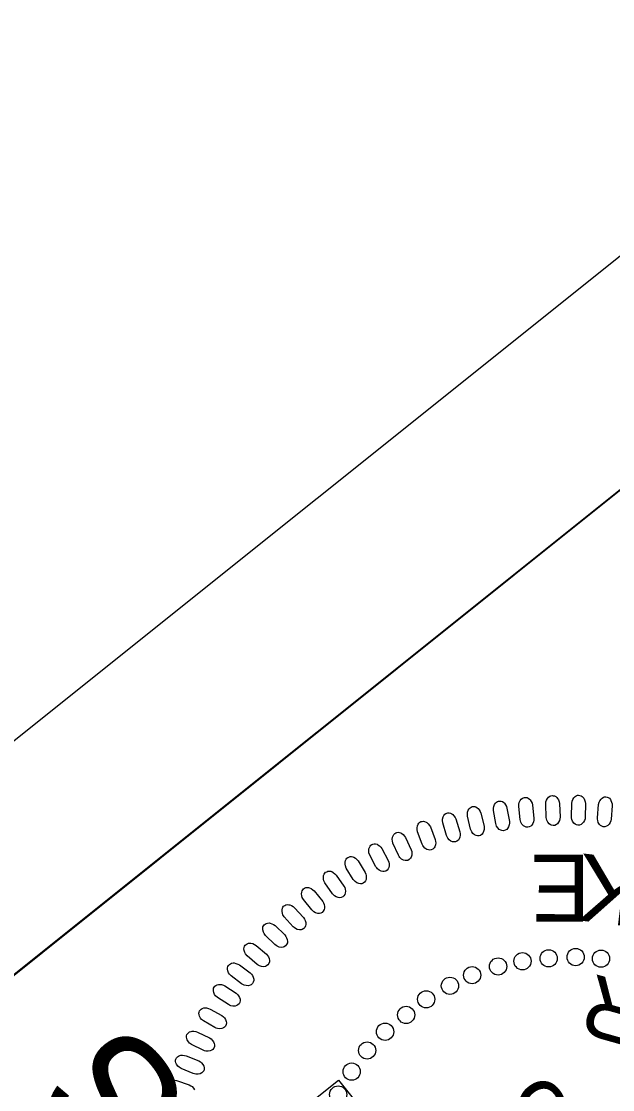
# Model space of a CAD drawing. Extents: x 473437 to 475344, y 504319 to 506318.
# Drawn here: x 473525.9 to 473580.9, y 505671.2 to 505770.6 of the extents above; entities that cross this region are included whole.
import ezdxf

# ---------------------------------------------------------------- set-up
doc = ezdxf.new("R2010")
doc.units = 0
for name, color, linetype in [('Sheet PE Seal Cell', 7, 'Continuous'), ('Sheet Plan CELL', 7, 'Continuous'), ('Sheet Plot Border Outside CELL', 7, 'Continuous'), ('Sheet Sticker Incomplete CELL', 7, 'Continuous')]:
    doc.layers.add(name, color=color, linetype=linetype)

msp = doc.modelspace()

# ---------------------------------------------------------------- linework, layer by layer
at = {"layer": 'Sheet PE Seal Cell'}
for points in [[(473572.264, 505696.325), (473572.13, 505697.544), (473572.143, 505697.766), (473572.179, 505697.911), (473572.273, 505698.092), (473572.357, 505698.211), (473572.461, 505698.303), (473572.56, 505698.353), (473572.67, 505698.385), (473572.783, 505698.378), (473572.905, 505698.361), (473573.016, 505698.313), (473573.13, 505698.225), (473573.199, 505698.153), (473573.282, 505698.011), (473573.361, 505697.839), (473573.401, 505697.683), (473573.545, 505696.434), (473573.541, 505696.264), (473573.511, 505696.12), (473573.44, 505695.952), (473573.344, 505695.801), (473573.256, 505695.711), (473573.106, 505695.634), (473572.959, 505695.598), (473572.807, 505695.622), (473572.697, 505695.66), (473572.56, 505695.745), (473572.423, 505695.9), (473572.336, 505696.072), (473572.292, 505696.197)], [(473574.687, 505696.522), (473574.631, 505697.747), (473574.658, 505697.968), (473574.703, 505698.11), (473574.808, 505698.284), (473574.9, 505698.398), (473575.009, 505698.484), (473575.11, 505698.528), (473575.222, 505698.553), (473575.335, 505698.538), (473575.456, 505698.514), (473575.563, 505698.46), (473575.671, 505698.364), (473575.736, 505698.287), (473575.81, 505698.141), (473575.878, 505697.964), (473575.908, 505697.806), (473575.973, 505696.552), (473575.959, 505696.381), (473575.92, 505696.24), (473575.838, 505696.076), (473575.733, 505695.931), (473575.639, 505695.847), (473575.485, 505695.78), (473575.337, 505695.754), (473575.186, 505695.786), (473575.079, 505695.831), (473574.947, 505695.925), (473574.82, 505696.088), (473574.744, 505696.265), (473574.709, 505696.393)], [(473577.034, 505696.6), (473577.054, 505697.826), (473577.095, 505698.045), (473577.149, 505698.184), (473577.264, 505698.352), (473577.363, 505698.46), (473577.477, 505698.538), (473577.582, 505698.576), (473577.695, 505698.593), (473577.806, 505698.571), (473577.925, 505698.54), (473578.028, 505698.479), (473578.132, 505698.377), (473578.19, 505698.296), (473578.255, 505698.145), (473578.312, 505697.965), (473578.332, 505697.805), (473578.319, 505696.548), (473578.293, 505696.379), (473578.246, 505696.241), (473578.154, 505696.083), (473578.04, 505695.945), (473577.94, 505695.867), (473577.783, 505695.809), (473577.633, 505695.793), (473577.484, 505695.835), (473577.38, 505695.886), (473577.255, 505695.988), (473577.138, 505696.159), (473577.074, 505696.34), (473577.046, 505696.47)], [(473579.444, 505696.487), (473579.541, 505697.71), (473579.595, 505697.926), (473579.659, 505698.061), (473579.784, 505698.221), (473579.89, 505698.322), (473580.008, 505698.393), (473580.115, 505698.424), (473580.229, 505698.435), (473580.339, 505698.407), (473580.456, 505698.367), (473580.555, 505698.3), (473580.651, 505698.191), (473580.705, 505698.107), (473580.76, 505697.953), (473580.806, 505697.769), (473580.815, 505697.608), (473580.723, 505696.355), (473580.687, 505696.188), (473580.631, 505696.052), (473580.529, 505695.9), (473580.407, 505695.77), (473580.303, 505695.698), (473580.142, 505695.65), (473579.991, 505695.643), (473579.846, 505695.695), (473579.745, 505695.753), (473579.626, 505695.862), (473579.521, 505696.04), (473579.468, 505696.225), (473579.448, 505696.356)], [(473567.65, 505695.432), (473567.365, 505696.625), (473567.351, 505696.847), (473567.368, 505696.995), (473567.438, 505697.186), (473567.507, 505697.315), (473567.598, 505697.419), (473567.69, 505697.482), (473567.795, 505697.527), (473567.908, 505697.534), (473568.032, 505697.532), (473568.147, 505697.499), (473568.272, 505697.426), (473568.349, 505697.363), (473568.449, 505697.233), (473568.549, 505697.072), (473568.608, 505696.922), (473568.908, 505695.702), (473568.926, 505695.532), (473568.914, 505695.385), (473568.864, 505695.21), (473568.787, 505695.048), (473568.712, 505694.948), (473568.573, 505694.853), (473568.432, 505694.798), (473568.278, 505694.802), (473568.164, 505694.827), (473568.017, 505694.894), (473567.861, 505695.031), (473567.754, 505695.19), (473567.695, 505695.309)], [(473569.982, 505695.955), (473569.773, 505697.164), (473569.772, 505697.386), (473569.799, 505697.533), (473569.881, 505697.719), (473569.958, 505697.844), (473570.055, 505697.942), (473570.151, 505697.999), (473570.258, 505698.038), (473570.372, 505698.037), (473570.495, 505698.028), (473570.607, 505697.987), (473570.728, 505697.907), (473570.801, 505697.839), (473570.893, 505697.702), (473570.982, 505697.535), (473571.032, 505697.383), (473571.255, 505696.145), (473571.262, 505695.975), (473571.241, 505695.829), (473571.18, 505695.657), (473571.093, 505695.5), (473571.011, 505695.405), (473570.867, 505695.319), (473570.723, 505695.274), (473570.569, 505695.288), (473570.457, 505695.32), (473570.315, 505695.396), (473570.168, 505695.542), (473570.071, 505695.708), (473570.019, 505695.83)], [(473565.421, 505694.829), (473565.061, 505696.001), (473565.033, 505696.222), (473565.041, 505696.371), (473565.099, 505696.566), (473565.16, 505696.699), (473565.244, 505696.808), (473565.332, 505696.877), (473565.433, 505696.929), (473565.546, 505696.943), (473565.669, 505696.949), (473565.787, 505696.923), (473565.916, 505696.858), (473565.997, 505696.799), (473566.105, 505696.676), (473566.215, 505696.522), (473566.283, 505696.376), (473566.659, 505695.177), (473566.687, 505695.008), (473566.685, 505694.862), (473566.646, 505694.683), (473566.58, 505694.517), (473566.511, 505694.411), (473566.378, 505694.308), (473566.241, 505694.246), (473566.086, 505694.24), (473565.971, 505694.257), (473565.821, 505694.315), (473565.657, 505694.442), (473565.539, 505694.594), (473565.473, 505694.709)], [(473563.142, 505694.03), (473562.709, 505695.179), (473562.667, 505695.397), (473562.666, 505695.546), (473562.711, 505695.745), (473562.763, 505695.881), (473562.841, 505695.996), (473562.924, 505696.07), (473563.022, 505696.128), (473563.134, 505696.149), (473563.257, 505696.163), (473563.375, 505696.144), (473563.509, 505696.087), (473563.593, 505696.034), (473563.708, 505695.917), (473563.828, 505695.771), (473563.905, 505695.629), (473564.355, 505694.456), (473564.394, 505694.29), (473564.401, 505694.143), (473564.374, 505693.962), (473564.318, 505693.792), (473564.255, 505693.683), (473564.129, 505693.572), (473563.996, 505693.5), (473563.843, 505693.485), (473563.727, 505693.495), (473563.573, 505693.543), (473563.401, 505693.66), (473563.275, 505693.804), (473563.202, 505693.915)], [(473560.936, 505692.999), (473560.432, 505694.118), (473560.377, 505694.333), (473560.366, 505694.481), (473560.399, 505694.682), (473560.443, 505694.822), (473560.513, 505694.941), (473560.591, 505695.02), (473560.685, 505695.084), (473560.795, 505695.112), (473560.917, 505695.134), (473561.037, 505695.123), (473561.173, 505695.075), (473561.261, 505695.027), (473561.384, 505694.917), (473561.512, 505694.779), (473561.598, 505694.643), (473562.121, 505693.5), (473562.17, 505693.336), (473562.186, 505693.19), (473562.17, 505693.008), (473562.125, 505692.835), (473562.07, 505692.722), (473561.951, 505692.603), (473561.823, 505692.523), (473561.67, 505692.498), (473561.554, 505692.501), (473561.397, 505692.539), (473561.219, 505692.645), (473561.083, 505692.781), (473561.004, 505692.887)], [(473558.84, 505691.938), (473558.268, 505693.022), (473558.198, 505693.234), (473558.178, 505693.381), (473558.199, 505693.584), (473558.234, 505693.727), (473558.295, 505693.85), (473558.369, 505693.934), (473558.459, 505694.004), (473558.567, 505694.038), (473558.687, 505694.068), (473558.808, 505694.064), (473558.947, 505694.024), (473559.037, 505693.982), (473559.166, 505693.881), (473559.303, 505693.75), (473559.397, 505693.62), (473559.991, 505692.512), (473560.051, 505692.352), (473560.076, 505692.207), (473560.071, 505692.024), (473560.037, 505691.849), (473559.989, 505691.733), (473559.878, 505691.606), (473559.755, 505691.519), (473559.604, 505691.484), (473559.488, 505691.479), (473559.33, 505691.508), (473559.145, 505691.602), (473559.001, 505691.73), (473558.915, 505691.831)], [(473556.729, 505690.756), (473556.089, 505691.803), (473556.006, 505692.009), (473555.978, 505692.156), (473555.984, 505692.359), (473556.01, 505692.504), (473556.065, 505692.63), (473556.133, 505692.718), (473556.219, 505692.794), (473556.324, 505692.835), (473556.442, 505692.872), (473556.562, 505692.876), (473556.704, 505692.845), (473556.796, 505692.809), (473556.932, 505692.716), (473557.076, 505692.594), (473557.179, 505692.47), (473557.841, 505691.401), (473557.911, 505691.245), (473557.945, 505691.102), (473557.951, 505690.92), (473557.929, 505690.742), (473557.888, 505690.623), (473557.785, 505690.49), (473557.668, 505690.396), (473557.519, 505690.352), (473557.404, 505690.339), (473557.244, 505690.358), (473557.054, 505690.441), (473556.902, 505690.558), (473556.809, 505690.654)], [(473554.798, 505689.424), (473554.093, 505690.428), (473553.999, 505690.629), (473553.96, 505690.773), (473553.955, 505690.977), (473553.971, 505691.123), (473554.017, 505691.252), (473554.08, 505691.345), (473554.161, 505691.426), (473554.264, 505691.473), (473554.379, 505691.518), (473554.499, 505691.529), (473554.642, 505691.507), (473554.736, 505691.476), (473554.878, 505691.393), (473555.03, 505691.28), (473555.14, 505691.162), (473555.868, 505690.138), (473555.946, 505689.986), (473555.99, 505689.846), (473556.008, 505689.664), (473555.996, 505689.486), (473555.963, 505689.364), (473555.869, 505689.225), (473555.757, 505689.123), (473555.612, 505689.07), (473555.498, 505689.05), (473555.337, 505689.059), (473555.142, 505689.129), (473554.983, 505689.238), (473554.885, 505689.326)], [(473552.872, 505687.925), (473552.105, 505688.883), (473551.998, 505689.078), (473551.951, 505689.219), (473551.933, 505689.422), (473551.94, 505689.568), (473551.978, 505689.701), (473552.035, 505689.797), (473552.11, 505689.883), (473552.21, 505689.937), (473552.322, 505689.989), (473552.441, 505690.007), (473552.585, 505689.994), (473552.682, 505689.97), (473552.828, 505689.895), (473552.987, 505689.792), (473553.104, 505689.682), (473553.895, 505688.705), (473553.983, 505688.559), (473554.035, 505688.421), (473554.065, 505688.24), (473554.064, 505688.062), (473554.038, 505687.938), (473553.953, 505687.793), (473553.849, 505687.685), (473553.707, 505687.623), (473553.594, 505687.596), (473553.433, 505687.594), (473553.233, 505687.653), (473553.069, 505687.751), (473552.964, 505687.833)], [(473551.145, 505686.352), (473550.321, 505687.261), (473550.202, 505687.448), (473550.146, 505687.586), (473550.115, 505687.788), (473550.113, 505687.934), (473550.143, 505688.068), (473550.193, 505688.168), (473550.263, 505688.258), (473550.359, 505688.319), (473550.468, 505688.377), (473550.585, 505688.403), (473550.73, 505688.4), (473550.828, 505688.381), (473550.978, 505688.316), (473551.144, 505688.223), (473551.267, 505688.12), (473552.118, 505687.195), (473552.215, 505687.054), (473552.275, 505686.92), (473552.316, 505686.742), (473552.327, 505686.564), (473552.309, 505686.439), (473552.233, 505686.289), (473552.135, 505686.174), (473551.998, 505686.103), (473551.887, 505686.069), (473551.726, 505686.058), (473551.524, 505686.103), (473551.353, 505686.191), (473551.244, 505686.267)], [(473549.451, 505684.685), (473548.572, 505685.539), (473548.44, 505685.719), (473548.376, 505685.853), (473548.332, 505686.052), (473548.321, 505686.198), (473548.342, 505686.334), (473548.386, 505686.437), (473548.45, 505686.531), (473548.542, 505686.598), (473548.648, 505686.663), (473548.763, 505686.697), (473548.908, 505686.702), (473549.006, 505686.689), (473549.161, 505686.633), (473549.332, 505686.551), (473549.462, 505686.456), (473550.369, 505685.586), (473550.474, 505685.452), (473550.543, 505685.322), (473550.595, 505685.147), (473550.617, 505684.969), (473550.607, 505684.844), (473550.541, 505684.69), (473550.45, 505684.568), (473550.318, 505684.489), (473550.209, 505684.449), (473550.049, 505684.427), (473549.844, 505684.459), (473549.669, 505684.536), (473549.555, 505684.606)], [(473547.796, 505682.85), (473546.864, 505683.647), (473546.722, 505683.818), (473546.649, 505683.948), (473546.593, 505684.144), (473546.573, 505684.289), (473546.585, 505684.427), (473546.623, 505684.531), (473546.681, 505684.63), (473546.769, 505684.702), (473546.87, 505684.773), (473546.982, 505684.814), (473547.126, 505684.829), (473547.226, 505684.823), (473547.384, 505684.776), (473547.559, 505684.705), (473547.694, 505684.619), (473548.655, 505683.807), (473548.769, 505683.68), (473548.845, 505683.555), (473548.908, 505683.383), (473548.941, 505683.207), (473548.939, 505683.082), (473548.883, 505682.923), (473548.8, 505682.797), (473548.673, 505682.709), (473548.567, 505682.662), (473548.409, 505682.63), (473548.202, 505682.65), (473548.021, 505682.715), (473547.904, 505682.777)], [(473546.354, 505681.043), (473545.374, 505681.781), (473545.222, 505681.942), (473545.141, 505682.068), (473545.072, 505682.26), (473545.043, 505682.403), (473545.047, 505682.541), (473545.078, 505682.648), (473545.13, 505682.75), (473545.213, 505682.828), (473545.309, 505682.905), (473545.419, 505682.953), (473545.562, 505682.976), (473545.662, 505682.976), (473545.822, 505682.94), (473546.002, 505682.88), (473546.142, 505682.802), (473547.151, 505682.053), (473547.273, 505681.933), (473547.357, 505681.813), (473547.431, 505681.645), (473547.475, 505681.472), (473547.481, 505681.346), (473547.434, 505681.185), (473547.36, 505681.053), (473547.238, 505680.958), (473547.136, 505680.905), (473546.98, 505680.863), (473546.773, 505680.869), (473546.589, 505680.923), (473546.467, 505680.978)], [(473545.123, 505679.104), (473544.098, 505679.778), (473543.936, 505679.93), (473543.847, 505680.05), (473543.768, 505680.237), (473543.729, 505680.379), (473543.724, 505680.517), (473543.748, 505680.625), (473543.794, 505680.73), (473543.872, 505680.813), (473543.963, 505680.896), (473544.07, 505680.951), (473544.211, 505680.983), (473544.31, 505680.99), (473544.473, 505680.964), (473544.655, 505680.915), (473544.801, 505680.846), (473545.855, 505680.162), (473545.984, 505680.05), (473546.075, 505679.935), (473546.16, 505679.773), (473546.215, 505679.603), (473546.228, 505679.477), (473546.192, 505679.313), (473546.126, 505679.177), (473546.011, 505679.074), (473545.912, 505679.015), (473545.758, 505678.963), (473545.552, 505678.956), (473545.364, 505678.999), (473545.239, 505679.045)], [(473543.863, 505676.975), (473542.797, 505677.584), (473542.626, 505677.726), (473542.53, 505677.84), (473542.438, 505678.021), (473542.392, 505678.16), (473542.378, 505678.297), (473542.395, 505678.408), (473542.433, 505678.515), (473542.507, 505678.602), (473542.592, 505678.692), (473542.695, 505678.753), (473542.835, 505678.794), (473542.933, 505678.807), (473543.097, 505678.791), (473543.282, 505678.754), (473543.431, 505678.694), (473544.526, 505678.077), (473544.662, 505677.973), (473544.761, 505677.865), (473544.855, 505677.708), (473544.921, 505677.542), (473544.942, 505677.417), (473544.916, 505677.251), (473544.859, 505677.111), (473544.75, 505677.002), (473544.655, 505676.935), (473544.505, 505676.874), (473544.299, 505676.855), (473544.11, 505676.885), (473543.982, 505676.924)], [(473542.787, 505674.86), (473541.686, 505675.401), (473541.506, 505675.531), (473541.403, 505675.639), (473541.3, 505675.815), (473541.245, 505675.951), (473541.222, 505676.087), (473541.233, 505676.198), (473541.264, 505676.308), (473541.332, 505676.399), (473541.412, 505676.493), (473541.511, 505676.561), (473541.647, 505676.611), (473541.745, 505676.629), (473541.909, 505676.624), (473542.096, 505676.598), (473542.249, 505676.548), (473543.381, 505676.001), (473543.523, 505675.906), (473543.629, 505675.804), (473543.732, 505675.654), (473543.808, 505675.491), (473543.837, 505675.369), (473543.821, 505675.201), (473543.773, 505675.058), (473543.672, 505674.942), (473543.581, 505674.87), (473543.435, 505674.8), (473543.23, 505674.768), (473543.039, 505674.786), (473542.91, 505674.817)], [(473541.853, 505672.694), (473540.72, 505673.164), (473540.532, 505673.283), (473540.422, 505673.384), (473540.308, 505673.553), (473540.245, 505673.685), (473540.214, 505673.82), (473540.218, 505673.932), (473540.242, 505674.042), (473540.304, 505674.138), (473540.377, 505674.237), (473540.472, 505674.311), (473540.605, 505674.37), (473540.701, 505674.394), (473540.865, 505674.399), (473541.054, 505674.385), (473541.21, 505674.345), (473542.373, 505673.87), (473542.521, 505673.784), (473542.633, 505673.689), (473542.746, 505673.545), (473542.832, 505673.389), (473542.869, 505673.268), (473542.864, 505673.1), (473542.825, 505672.954), (473542.731, 505672.832), (473542.644, 505672.754), (473542.503, 505672.674), (473542.301, 505672.629), (473542.109, 505672.636), (473541.978, 505672.658)]]:
    msp.add_lwpolyline(points, close=True, dxfattribs=at)
msp.add_lwpolyline([(473539.445, 505671.189), (473539.373, 505671.317), (473539.334, 505671.449), (473539.33, 505671.561), (473539.348, 505671.673), (473539.403, 505671.773), (473539.47, 505671.876), (473539.561, 505671.956), (473539.69, 505672.023), (473539.784, 505672.053), (473539.948, 505672.068), (473540.137, 505672.066), (473540.295, 505672.036), (473541.486, 505671.635), (473541.639, 505671.559), (473541.756, 505671.471), (473541.878, 505671.334), (473541.974, 505671.183)], dxfattribs=at)
for centre in [(473577.416, 505683.527), (473570.207, 505682.655), (473572.471, 505683.14), (473574.909, 505683.408), (473579.78, 505683.378), (473567.793, 505681.846), (473565.728, 505680.857), (473563.519, 505679.6), (473561.655, 505678.146), (473559.695, 505676.579), (473558.027, 505674.837), (473556.589, 505672.871), (473555.332, 505670.744)]:
    msp.add_circle(centre, 0.801, dxfattribs=at)
at = {"layer": 'Sheet Plan CELL'}
for points in [[(473465.55, 505634.173), (474402.849, 504463.027), (475222.63, 505119.12), (474285.347, 506290.246)], [(473557.377, 505579.55), (473494.89, 505657.607), (473582.726, 505727.92), (473645.22, 505649.853)]]:
    msp.add_lwpolyline(points, close=True, dxfattribs=at)
at = {"layer": 'Sheet Plot Border Outside CELL'}
msp.add_lwpolyline([(475344.237, 505003.203), (474292.301, 506317.586), (473437.386, 505633.375), (474489.322, 504318.991)], close=True, dxfattribs=at)
at = {"layer": 'Sheet Sticker Incomplete CELL'}
msp.add_lwpolyline([(473647.22, 505557.313), (473628.873, 505542.629), (473537.02, 505657.398), (473555.367, 505672.082)], close=True, dxfattribs=at)

# ---------------------------------------------------------------- texts
at = {"layer": 'Sheet PE Seal Cell'}
for s, height, rotation, p in [('E', 6.236, 179.93948, (473578.791, 505693.061)), ('K', 6.236, 173.09383, (473583.553, 505692.511)), ('R', 5.669, 164.33479, (473584.304, 505680.529)), ('46155', 6.2363, 128.65259, (473588.84, 505654.883))]:
    msp.add_text(s, height=height, rotation=rotation, dxfattribs=at).set_placement(p)
at = {"layer": 'Sheet Sticker Incomplete CELL'}
msp.add_text('INCOMPLETE PLANS', height=11.52, rotation=128.67122, dxfattribs=at).set_placement((473632.493, 505556.99))

doc.saveas('drawing.dxf')
